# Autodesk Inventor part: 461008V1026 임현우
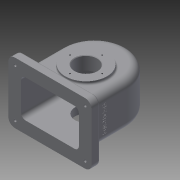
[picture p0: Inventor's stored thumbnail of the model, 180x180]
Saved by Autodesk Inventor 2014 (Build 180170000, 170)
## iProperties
Created: 2016-10
Part Number: 461008V1026 임현우
Material: 일반
Document SubType Name: Modeling
Designer: 703-18
Density: 1 g/cm^3
Appearance: 기본값
Author: 703-18
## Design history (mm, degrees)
sketch "스케치1"
  geometry: L1 (-58, 0)-(-58, -80); L2 (58, 0)-(58, -80); L3 (-58, -80)-(58, -80); A1 r 58 centre (0, 0) between (58, 0) and (-58, 0); 1 further point
  constraints: 6 end point, 2 point on circle, 2 tangent, 1 centre point, 1 coincident, 1 parallel, 1 perpendicular, 1 vertical
  dimensions: "d0" = 116 diameter of A1; "d1" = 80 distance of L1.start L1.end
extrude "돌출1" new body sketch "스케치1" stored distance "d2" = 77; taper "d3" = 0 deg
fillet "모깎기1" dims "d4" = 13
node "작업 평면1"
sketch "스케치2"
  geometry: L1 (58, 0)-(58, -80) reference; L2 (58, -80)-(-58, -80) reference; L3 (-58, -80)-(-58, 0) reference; L4 (52, 0)-(52, -80); L5 (-52, -80)-(-52, 0); L6 (-52, -80)-(52, -80); A1 r 58 centre (0, 0) between (58, 0) and (-58, 0) reference; A2 r 52 centre (0, 0) between (52, 0) and (-52, 0); 1 further point
  constraints: 6 end point, 2 point on circle, 2 point on line, 1 centre point, 1 collinear
  dimensions: "d6" = 6 radial gap between concentric circles of A1 A2
extrude "돌출2" cut sketch "스케치2" stored distance "d7" = 67; taper "d8" = 0 deg
fillet "모깎기2" dims "d9" = 8
sketch "스케치3"
  geometry: L1 (89, -72)-(1, -72) reference; L2 (-7, -64)-(-7, -13) reference; L3 (1, -5)-(89, -5) reference; L4 (97, -13)-(97, -64) reference; L5 (-30, 16.5)-(120, 16.5); L6 (120, 16.5)-(120, -93.5); L7 (120, -93.5)-(-30, -93.5); L8 (-30, -93.5)-(-30, 16.5); A1 r 8 centre (1, -64) between (-7, -64) and (1, -72) reference; A2 r 8 centre (1, -13) between (1, -5) and (-7, -13) reference; A3 r 8 centre (89, -13) between (97, -13) and (89, -5) reference; A4 r 8 centre (89, -64) between (89, -72) and (97, -64) reference; 3 further points
  constraints: 8 end point, 2 midpoint, 2 parallel, 1 horizontal, 1 horizontal alignment, 1 perpendicular, 1 vertical alignment
  dimensions: "d10" = 150 distance of L5.start L5.end; "d11" = 110 distance of L5.end L6.end
extrude "돌출3" join sketch "스케치3" distance "d12" = 15; taper "d13" = 0 deg
fillet "모깎기3" dims "d14" = 12
node "작업 평면2"
sketch "스케치4"
  geometry: C1 r 6 at (63, 55); 1 further point
  constraints: 1 centre point, 1 coincident
  dimensions: "d16" = 12 diameter of C1
extrude "돌출4" join sketch "스케치4" distance "d17" = 12; taper "d18" = 10 deg
fillet "모깎기4" dims "d19" = 3
fillet "모깎기5" dims "d20" = 3
node "작업 평면3"
sketch "스케치5"
  geometry: L1 (52, -25.5)-(52, 25.5) reference; L2 (44, 33.5)-(-80, 33.5) reference; L3 (-80, 33.5)-(-80, 55) reference; L4 (-80, 55)-(-68, 55) reference; L5 (-65, 52)-(-65, 38.5) reference; L6 (-65, 38.5)-(45, 38.5) reference; L7 (58, 25.5)-(58, 9.575) reference; L8 (60.479, 6.621)-(64, 6) reference; L9 (64, 6)-(64, -6) reference; L10 (64, -6)-(60.479, -6.621) reference; L11 (58, -9.575)-(58, -25.5) reference; L12 (45, -38.5)-(-65, -38.5) reference; L13 (-65, -38.5)-(-65, -52) reference; L14 (-68, -55)-(-80, -55) reference; L15 (-80, -55)-(-80, -33.5) reference; L16 (-80, -33.5)-(44, -33.5) reference; L17 (-43, 19.5)-(-15, 19.5); L18 (-15, 43.5)-(-15, 19.5); L19 (-15, 43.5)-(-52.5, 43.5); L20 (-52.5, 43.5)-(-52.5, 38.5); L21 (-43, 19.5)-(-54.747, 33.5); L22 (-52.5, 38.5)-(-54.747, 33.5); A1 r 8 centre (44, -25.5) between (44, -33.5) and (52, -25.5) reference; A2 r 8 centre (44, 25.5) between (52, 25.5) and (44, 33.5) reference; A3 r 3 centre (-68, 52) between (-65, 52) and (-68, 55) reference; A4 r 13 centre (45, 25.5) between (58, 25.5) and (45, 38.5) reference; A5 r 13 centre (45, -25.5) between (45, -38.5) and (58, -25.5) reference; A6 r 3 centre (-68, -52) between (-68, -55) and (-65, -52) reference; 1 further point
  constraints: 12 end point, 3 perpendicular, 2 point on line, 2 other
  dimensions: "d25" = 37.5 distance of L18.start L19.end; "d26" = 28 distance of L17.start L17.end
revolve "회전1" sketch "스케치5" stored, may be unused: angle "d28" = 90 deg
sketch "스케치6"
  geometry: L1 (52, -25.5)-(52, 25.5) reference; L2 (44, 33.5)-(24.747, 33.5) reference; L3 (24.747, 33.5)-(13, 19.5) reference; L4 (13, 19.5)-(-43, 19.5) reference; L5 (-43, 19.5)-(-54.747, 33.5) reference; L6 (-54.747, 33.5)-(-80, 33.5) reference; L7 (-80, 33.5)-(-80, 55) reference; L8 (-80, 55)-(-68, 55) reference; L9 (-65, 52)-(-65, 38.5) reference; L10 (-65, 38.5)-(-52.5, 38.5) reference; L11 (-52.5, 38.5)-(-52.5, 43.5) reference; L12 (-52.5, 43.5)-(22.5, 43.5) reference; L13 (22.5, 43.5)-(22.5, 38.5) reference; L14 (22.5, 38.5)-(45, 38.5) reference; L15 (58, 25.5)-(58, 9.575) reference; L16 (60.479, 6.621)-(64, 6) reference; L17 (64, 6)-(64, -6) reference; L18 (64, -6)-(60.479, -6.621) reference; L19 (58, -9.575)-(58, -25.5) reference; L20 (45, -38.5)-(-65, -38.5) reference; L21 (-65, -38.5)-(-65, -52) reference; L22 (-68, -55)-(-80, -55) reference; L23 (-80, -55)-(-80, -33.5) reference; L24 (-80, -33.5)-(44, -33.5) reference; L25 (-15, -33.5)-(-15, -48.5); L26 (-15, -48.5)-(16, -48.5); L27 (16, -48.5)-(16, -33.5); L28 (-15, -33.5)-(16, -33.5); A1 r 8 centre (44, -25.5) between (44, -33.5) and (52, -25.5) reference; A2 r 8 centre (44, 25.5) between (52, 25.5) and (44, 33.5) reference; A3 r 3 centre (-68, 52) between (-65, 52) and (-68, 55) reference; A4 r 13 centre (45, 25.5) between (58, 25.5) and (45, 38.5) reference; A5 r 13 centre (45, -25.5) between (45, -38.5) and (58, -25.5) reference; A6 r 3 centre (-68, -52) between (-68, -55) and (-65, -52) reference; 1 further point
  constraints: 8 end point, 2 perpendicular, 2 point on line, 1 collinear, 2 other
  dimensions: "d30" = 15 distance of L25.start L25.end; "d31" = 31 distance of L25.end L26.end
revolve "회전2" sketch "스케치6" stored, may be unused: angle "d32" = 90 deg
sketch "스케치7"
  geometry: C1 r 37.5 at (0, 0) reference; C2 r 20 at (0, 0); 1 further point
  constraints: 1 centre point, 1 coincident
  dimensions: "d33" = 40 diameter of C2
extrude "돌출5" cut sketch "스케치7" stored distance "d34" = 12; taper "d35" = 0 deg
sketch "스케치8" dims "d36" = 58
  geometry: L1 (0, 0)-(0, 29); C1 r 37.5 at (0, 0) reference; 1 further point
  constraints: 2 end point, 1 coincident, 1 vertical, 1 vertical alignment, 2 other
hole "구멍1" sketch "스케치8" at (0, 29) diameter "d37" = 2.459; stored, may be unused: countersink angle "d41" = 90 deg, drill point angle "d43" = 118 deg; dims "d38" = 6, "d39" = 4, "d40" = 2, "d42" = 8
sketch "스케치9" dims "d47" = 52
  geometry: L1 (0, 0)-(0, 26); C1 r 31 at (0, 0) reference; 1 further point
  constraints: 2 end point, 1 coincident, 1 vertical, 1 vertical alignment, 2 other
hole "구멍2" sketch "스케치9" at (0, 26) diameter "d48" = 2.459; stored, may be unused: countersink angle "d52" = 90 deg, drill point angle "d54" = 118 deg; dims "d49" = 6, "d50" = 4, "d51" = 2, "d53" = 8
fillet "모깎기6" dims "d58" = 3
fillet "모깎기7" dims "d59" = 3
fillet "모깎기8" dims "d60" = 3
chamfer "모따기1" distance "d61" = 1; stored, may be unused: second distance "d62" = 2, angle "d63" = 45 deg
sketch "스케치11"
  geometry: C1 r 6 at (-18, 81.5); C2 r 6 at (108, 81.5); C3 r 6 at (-18, -4.5); C4 r 6 at (108, -4.5); A1 r 9 centre (108, -4.5) between (108, -13.5) and (117, -4.5) reference; A2 r 9 centre (108, 81.5) between (117, 81.5) and (108, 90.5) reference; A3 r 9 centre (-18, 81.5) between (-18, 90.5) and (-27, 81.5) reference; A4 r 9 centre (-18, -4.5) between (-27, -4.5) and (-18, -13.5) reference; 1 further point
  constraints: 4 centre point, 4 coincident
  dimensions: "d71" = 12 diameter of C1; "d72" = 12 diameter of C2; "d73" = 12 diameter of C3; "d74" = 12 diameter of C4
extrude "돌출6" cut sketch "스케치11" distance "d75" = 5; taper "d76" = 0 deg
sketch "스케치12"
  geometry: C1 r 6 at (0, 0) reference; C2 r 2.5 at (0, 0); 1 further point
  constraints: 1 centre point, 1 coincident
  dimensions: "d77" = 5 diameter of C2
extrude "돌출7" cut sketch "스케치12" stored distance "d78" = 5; taper "d79" = 0 deg
sketch "스케치14"
  geometry: 2 further points
  constraints: 1 other
feature "엠보싱2" sketch "스케치14" dims "d91" = 0.5, "d92" = 0
sketch "스케치15"
  geometry: C1 r 6 at (0, 0) reference
hole "구멍4" sketch "스케치15" at (0, 0) diameter "d93" = 4.459; stored, may be unused: countersink angle "d97" = 90 deg, drill point angle "d99" = 118 deg; dims "d94" = 6, "d95" = 4, "d96" = 2, "d98" = 8
node "솔리드1"
pattern_circular "원형 패턴1" dims angle "d45" = 360 deg
pattern_circular "원형 패턴2" dims angle "d56" = 360 deg
pattern_linear "직사각형 패턴1" dims "d82" = 126, "d85" = 86
node "절단 모서리 투영1"
node "절단 모서리 투영2"
node "절단 모서리 투영3"
other parameters: "d5" = 0, "d15" = -144, "d21" = 0, "d27" = 50 deg
